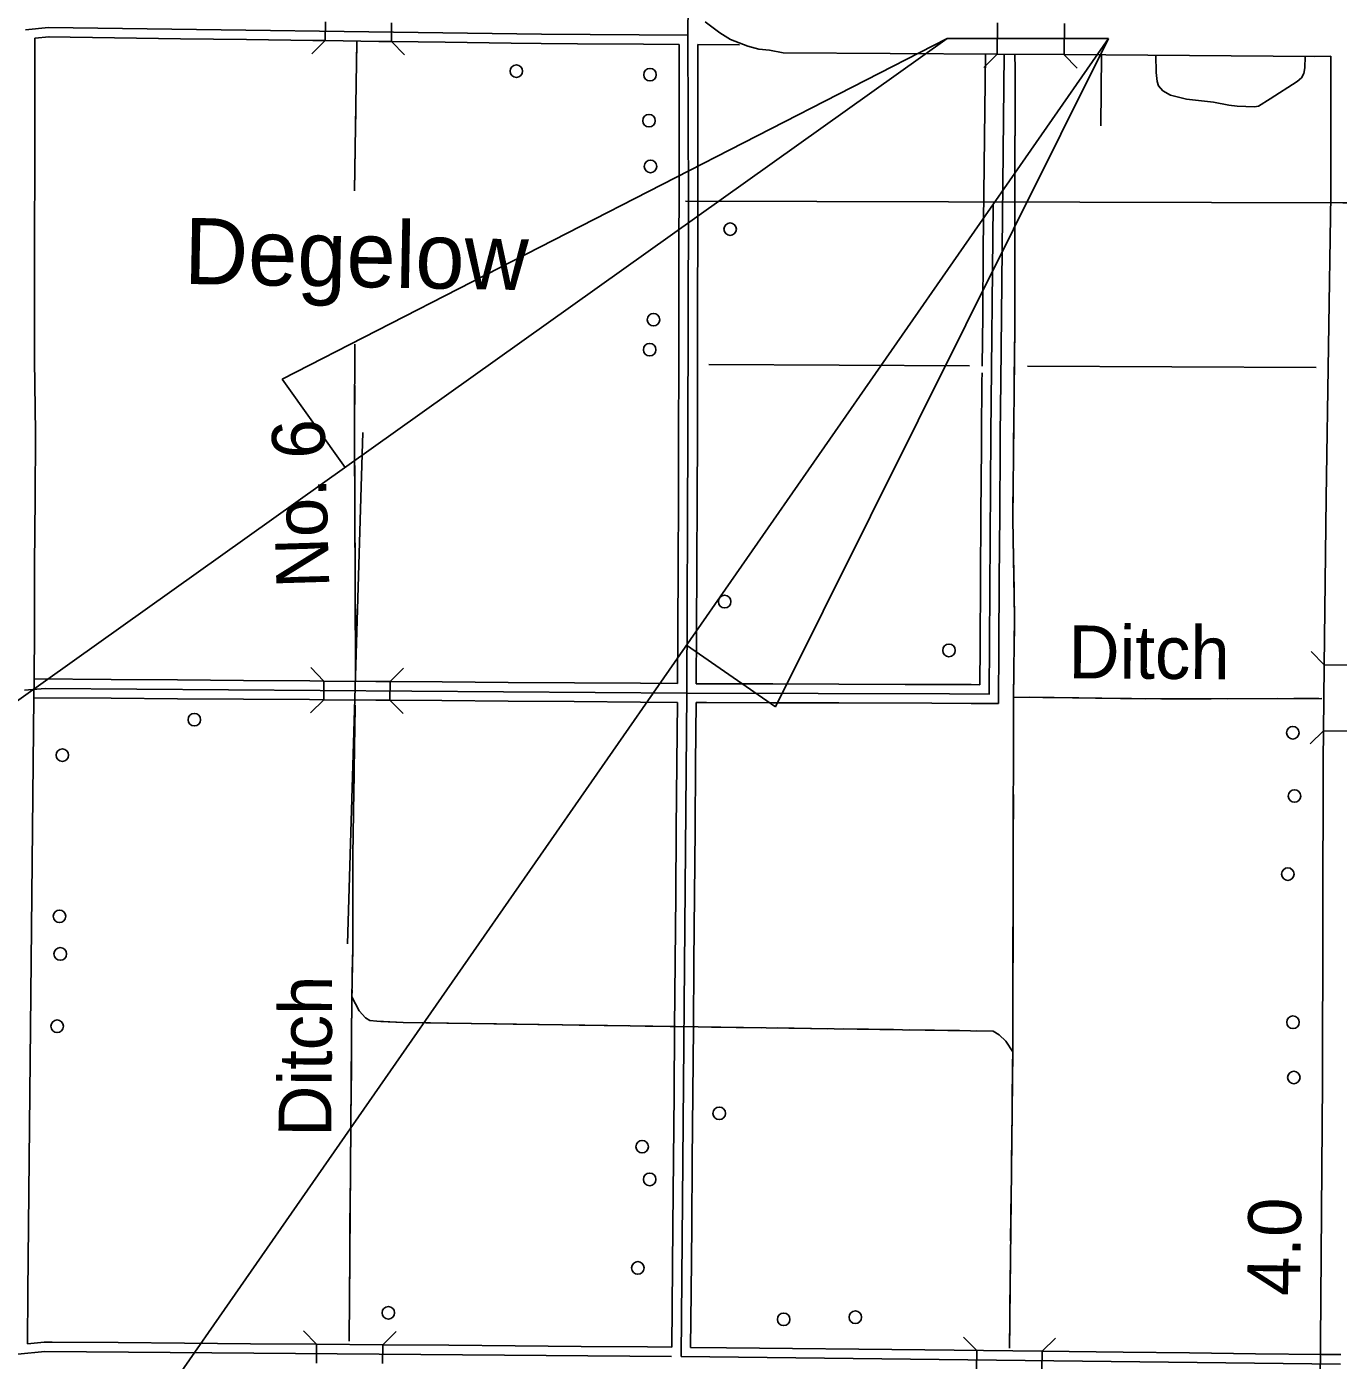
# Model space of a CAD drawing. Extents: x -4306 to 3843, y 131 to 8053.
# Drawn here: x -1926 to -251, y 1950 to 3654 of the extents above; entities that cross this region are included whole.
import ezdxf

# ---------------------------------------------------------------- set-up
doc = ezdxf.new("R2010")
doc.units = 0
for name, color, linetype in [('10', 7, 'Continuous'), ('24', 7, 'Continuous'), ('31', 7, 'Continuous'), ('32', 7, 'Continuous'), ('33', 7, 'Continuous'), ('35', 7, 'Continuous'), ('37', 7, 'Continuous'), ('38', 7, 'Continuous'), ('43', 7, 'Continuous'), ('48', 7, 'Continuous'), ('5', 7, 'Continuous'), ('56', 7, 'Continuous'), ('6', 7, 'Continuous'), ('R_No Plot', 7, 'Continuous')]:
    doc.layers.add(name, color=color, linetype=linetype)

msp = doc.modelspace()

# ---------------------------------------------------------------- linework, layer by layer
at = {"layer": '10'}
for p, q in [((-1040.8, 3645.6), (-1059.8, 3659.7)), ((-686.3, 3658.5), (-686.6, 3618.5)), ((-600.7, 3657.9), (-601, 3617.9)), ((-1027.4, 3637.4), (-1040.8, 3645.6)), ((-1005, 3628.7), (-1027.4, 3637.4)), ((-991.1, 3624.8), (-1005, 3628.7)), ((-977.5, 3623.7), (-991.1, 3624.8)), ((-959.9, 3620.4), (-977.5, 3623.7)), ((-686.6, 3618.5), (-959.9, 3620.4)), ((-687.1, 3618.5), (-600.9, 3617.9)), ((-601, 3617.9), (-281, 3615.7)), ((-281, 3615.7), (-260.7, 3616)), ((-260.7, 3616), (-260.6, 3613.9)), ((-260.6, 3613.9), (-260.3, 3438.2)), ((-260.3, 3438.2), (-266.6, 3051.5)), ((-269.9, 2753.7), (-269, 2836.4)), ((-229, 2837.7), (-269, 2838.1)), ((-269.9, 2754), (-229.9, 2753.6))]:
    msp.add_line(p, q, dxfattribs=at)
for points in [[(-269, 2836.4), (-266.6, 3051.5)], [(-314.4, 293.8), (-314.5, 305.1), (-312.3, 441.3), (-305.4, 600.9), (-302, 628.3), (-293.8, 664.7), (-283.6, 735.2), (-284.1, 861.9), (-282.2, 1054.1), (-278.9, 1201.3), (-280.3, 1434.8), (-278.7, 1599.9), (-273.4, 1758.6), (-274.2, 1917.6), (-271, 2305.4), (-270.3, 2716.6), (-269.9, 2753.7)]]:
    msp.add_lwpolyline(points, dxfattribs=at)
at = {"layer": '31'}
for p, q in [((-1545.1, 3635.8), (-1544.8, 3659.8)), ((-1460.5, 3634.7), (-1460.2, 3658.7)), ((-1915.8, 3638.8), (-1897.4, 3640.6)), ((-1898.7, 3640.5), (-1814.2, 3639.4)), ((-1814.2, 3639.4), (-1729.7, 3638.3)), ((-1560.8, 3636), (-1545.1, 3635.8)), ((-1545, 3635.8), (-1476.3, 3634.9)), ((-1476.3, 3634.9), (-1460.6, 3634.7)), ((-1460.6, 3634.7), (-1391.8, 3633.8)), ((-1222.8, 3631.8), (-1222.8, 3631.8)), ((-1222.8, 3631.8), (-1138.3, 3631.2)), ((-1138.3, 3631.2), (-1093, 3630.9)), ((-1069, 3630.8), (-1015.9, 3630.4)), ((-1915.9, 3558), (-1916, 3473.5)), ((-1916, 3473.5), (-1916.1, 3389)), ((-1093.1, 3388.4), (-1093, 3429.9)), ((-1069, 3429.9), (-1069, 3429.9)), ((-1916.3, 3227.2), (-1916.1, 3389)), ((-1916.1, 3389), (-1916.1, 3389)), ((-1093.1, 3388.4), (-1093.3, 3304)), ((-1069.1, 3388.4), (-1069.3, 3303.9)), ((-1093.3, 3304), (-1093.4, 3219.5)), ((-1069.3, 3303.9), (-1069.4, 3219.4)), ((-1916.3, 3227.2), (-1915.2, 3135.7)), ((-1915.2, 3135.7), (-1915.2, 3133.4)), ((-1915.2, 3133.4), (-1915.6, 3051)), ((-1093.9, 3050.5), (-1094.3, 2966)), ((-1069.9, 3050.4), (-1070.3, 2965.9)), ((-1094.3, 2966), (-1094.7, 2881.5)), ((-1070.3, 2965.9), (-1070.7, 2881.4)), ((-1916.5, 2882), (-1916.8, 2820.3)), ((-1916.8, 2820.3), (-1917, 2796.3)), ((-1917, 2796.3), (-1917.9, 2713)), ((-1095.8, 2712.6), (-1096.5, 2628.1)), ((-1071.8, 2712.4), (-1072.5, 2627.9)), ((-1096.5, 2628.1), (-1097.2, 2543.6)), ((-1072.5, 2627.9), (-1073.2, 2543.4)), ((-1919.6, 2544), (-1920.4, 2459.6)), ((-1920.4, 2459.6), (-1921.3, 2375.1)), ((-1098.7, 2374.7), (-1099.4, 2290.2)), ((-1074.7, 2374.5), (-1075.4, 2290)), ((-1099.4, 2290.2), (-1100.1, 2205.7)), ((-1075.4, 2290), (-1076.1, 2205.5)), ((-1923, 2206.1), (-1923.9, 2121.6)), ((-1100.1, 2205.7), (-1100.1, 2205.7)), ((-1923.9, 2121.6), (-1924.7, 2037.1)), ((-1077.6, 2036.5), (-1078.2, 1966.2)), ((-1032.5, 1965.7), (-1078.2, 1966.2)), ((-948, 1964.8), (-1032.5, 1965.7)), ((-629.3, 1961.2), (-779, 1962.9)), ((-713.1, 1938.1), (-712.8, 1962.1)), ((-629.6, 1937.2), (-629.3, 1961.2)), ((-629.3, 1961.2), (-525.6, 1960)), ((-525.6, 1960), (-441.1, 1959.1)), ((-356.6, 1958.1), (-441.1, 1959.1)), ((-272.1, 1957.2), (-356.6, 1958.1)), ((-247.9, 1956.9), (-272.1, 1957.2))]:
    msp.add_line(p, q, dxfattribs=at)
for points in [[(-1074.7, 3724.2), (-1078.5, 3721.7), (-1079.5, 3714.3), (-1081.3, 3682.4), (-1081.6, 3642.9), (-1081, 3429.9), (-1081.6, 3132.7)], [(-1915.9, 3558), (-1915.8, 3638.8)], [(-1729.7, 3638.3), (-1645.3, 3637.2)], [(-1645.3, 3637.2), (-1560.8, 3636)], [(-1391.8, 3633.8), (-1307.3, 3632.6)], [(-1307.3, 3632.6), (-1269.1, 3632.1), (-1222.8, 3631.8)], [(-1069, 3429.9), (-1069, 3429.9), (-1069.1, 3388.4)], [(-1093.4, 3219.5), (-1093.6, 3135)], [(-1069.6, 3134.9), (-1069.4, 3219.4)], [(-1093.6, 3135), (-1093.6, 3132.7), (-1093.9, 3050.5)], [(-1081.6, 3132.7), (-1083, 2802.2), (-1090.3, 1954.4)], [(-1069.9, 3050.4), (-1069.6, 3132.7), (-1069.6, 3134.9)], [(-1916.1, 2966.5), (-1915.6, 3051)], [(-1916.5, 2882), (-1916.1, 2966.5)], [(-1095, 2814.3), (-1094.7, 2881.5)], [(-1070.7, 2881.4), (-1071, 2814.2)], [(-1095.8, 2712.6), (-1095.1, 2790.3)], [(-1071.1, 2790.2), (-1071.8, 2712.4)], [(-1917.9, 2713), (-1918.7, 2628.5)], [(-1918.7, 2628.5), (-1919.6, 2544)], [(-1097.2, 2543.6), (-1098, 2459.2)], [(-1074, 2459), (-1073.2, 2543.4)], [(-1098, 2459.2), (-1098.7, 2374.7)], [(-1074.7, 2374.5), (-1074, 2459)], [(-1922.2, 2290.6), (-1921.3, 2375.1)], [(-1923, 2206.1), (-1922.2, 2290.6)], [(-1100.1, 2205.7), (-1100.9, 2121.2)], [(-1076.8, 2121), (-1076.1, 2205.5)], [(-1100.9, 2121.2), (-1102.2, 1966.5)], [(-1077.6, 2036.5), (-1076.8, 2121)], [(-1924.7, 2037.1), (-1925.4, 1970.7)], [(-863.5, 1963.8), (-948, 1964.8)], [(-779, 1962.9), (-863.5, 1963.8)]]:
    msp.add_lwpolyline(points, dxfattribs=at)
at = {"layer": '32'}
for p, q in [((-1927.7, 3649.7), (-1898.5, 3652.6)), ((-704.4, 3369.4), (-701.8, 3618.6)), ((-680.4, 3369.2), (-677.8, 3618.4)), ((-705.2, 3284.9), (-704.4, 3369.4)), ((-681.2, 3284.7), (-680.4, 3369.2)), ((-705.9, 3219.9), (-705.2, 3284.9)), ((-682.1, 3200.2), (-681.2, 3284.7)), ((-706.1, 3200.4), (-706, 3211.2)), ((-706.8, 3133.1), (-706.1, 3200.4)), ((-682.8, 3132.9), (-682.1, 3200.2)), ((-706.9, 3115.9), (-706.8, 3133.1)), ((-682.9, 3115.7), (-682.8, 3132.9)), ((-707.4, 3031.4), (-706.9, 3115.9)), ((-683.4, 3031.3), (-682.9, 3115.7)), ((-708, 2946.9), (-707.4, 3031.4)), ((-684, 2946.8), (-683.4, 3031.3)), ((-708.5, 2862.4), (-708, 2946.9)), ((-684.5, 2862.3), (-684, 2946.8)), ((-708.8, 2812.9), (-708.5, 2862.4)), ((-685, 2788.9), (-684.5, 2862.3)), ((-1916.8, 2820.3), (-1818.2, 2819.6)), ((-1818.2, 2819.6), (-1733.7, 2819)), ((-1733.7, 2819), (-1649.2, 2818.4)), ((-1649.2, 2818.4), (-1564.7, 2817.8)), ((-1564.7, 2817.8), (-1546.6, 2817.6)), ((-1546.8, 2793.6), (-1546.6, 2817.6)), ((-1546.6, 2817.6), (-1480.2, 2817.1)), ((-1480.2, 2817.1), (-1462.2, 2817)), ((-1462.4, 2793), (-1462.2, 2817)), ((-1462.3, 2817), (-1395.7, 2816.5)), ((-1395.7, 2816.5), (-1311.2, 2815.9)), ((-1311.2, 2815.9), (-1226.7, 2815.3)), ((-1226.7, 2815.3), (-1142.3, 2814.7)), ((-1142.3, 2814.7), (-1095, 2814.3)), ((-1071, 2814.2), (-1057.8, 2814.1)), ((-1057.8, 2814.1), (-973.3, 2813.9)), ((-973.3, 2813.9), (-888.8, 2813.6)), ((-888.8, 2813.6), (-804.4, 2813.3)), ((-804.4, 2813.3), (-747.6, 2813.1)), ((-747.6, 2813.1), (-719.9, 2813)), ((-719.9, 2813), (-708.8, 2812.9)), ((-1928.9, 2805.9), (-1902.7, 2808.2)), ((-1917, 2796.3), (-1818.3, 2795.6)), ((-1818.3, 2795.6), (-1733.8, 2795)), ((-1733.8, 2795), (-1649.4, 2794.4)), ((-1649.4, 2794.4), (-1564.9, 2793.8)), ((-1564.9, 2793.8), (-1546.8, 2793.6)), ((-1546.9, 2793.6), (-1480.4, 2793.1)), ((-1480.4, 2793.1), (-1462.4, 2793)), ((-1462.6, 2793), (-1395.9, 2792.5)), ((-1395.9, 2792.5), (-1311.4, 2791.9)), ((-1311.4, 2791.9), (-1226.9, 2791.3)), ((-1226.9, 2791.3), (-1142.4, 2790.7)), ((-1142.4, 2790.7), (-1095.1, 2790.3)), ((-1071.1, 2790.2), (-1057.9, 2790.1)), ((-1057.9, 2790.1), (-973.4, 2789.8)), ((-973.4, 2789.8), (-888.9, 2789.6)), ((-888.9, 2789.6), (-770.3, 2789.2)), ((-770.3, 2789.2), (-719.9, 2789)), ((-719.9, 2789), (-685, 2788.9)), ((-1925.4, 1970.7), (-1903.9, 1973)), ((-1903.9, 1973), (-1893.9, 1972.9)), ((-1893.9, 1972.9), (-1809.4, 1972.3)), ((-1809.4, 1972.3), (-1724.9, 1971.6)), ((-1724.9, 1971.6), (-1640.4, 1970.9)), ((-1640.4, 1970.9), (-1555.9, 1970.2)), ((-1556.1, 1946.2), (-1555.9, 1970.2)), ((-1555.9, 1970.2), (-1471.4, 1969.5)), ((-1471.6, 1945.5), (-1471.4, 1969.5)), ((-1471.4, 1969.5), (-1386.9, 1968.8)), ((-1386.9, 1968.8), (-1302.4, 1968.1)), ((-1302.4, 1968.1), (-1218, 1967.4)), ((-1218, 1967.4), (-1133.5, 1966.7)), ((-1133.5, 1966.7), (-1102.2, 1966.5)), ((-248.2, 1944.9), (-1090.3, 1954.4))]:
    msp.add_line(p, q, dxfattribs=at)
for points in [[(-1898.5, 3652.6), (-1268.9, 3644.1)], [(-1268.9, 3644.1), (-1081.6, 3642.9)], [(-694.8, 3133), (-691.8, 3425.9)], [(-747.7, 2801.1), (-696.9, 2800.9), (-694.8, 3133)], [(-1902.7, 2808.2), (-1083, 2802.2), (-747.7, 2801.1)], [(-2400.7, 1957.8), (-1937.5, 1957.3), (-1903.3, 1961)], [(-1903.3, 1961), (-1102.5, 1954.5)]]:
    msp.add_lwpolyline(points, dxfattribs=at)
at = {"layer": '33'}
for p, q in [((-1093, 3630.9), (-1093, 3429.9)), ((-1069, 3630.8), (-1069, 3429.9)), ((-553.4, 3617.5), (-554.1, 3527)), ((-483.8, 3594.9), (-484, 3617.1)), ((-293.2, 3615.7), (-293.7, 3601.2)), ((-293.7, 3601.2), (-295.1, 3593.8)), ((-482.5, 3583.7), (-483.8, 3594.9)), ((-480.7, 3578.1), (-482.5, 3583.7)), ((-303.4, 3583.5), (-338, 3561.3)), ((-297.9, 3588.5), (-303.4, 3583.5)), ((-295.1, 3593.8), (-297.9, 3588.5)), ((-475.3, 3571.6), (-480.7, 3578.1)), ((-465.4, 3566.2), (-475.3, 3571.6)), ((-444.9, 3561.1), (-465.4, 3566.2)), ((-410.2, 3557), (-444.9, 3561.1)), ((-390.6, 3553.2), (-410.2, 3557)), ((-380, 3551.9), (-390.6, 3553.2)), ((-358.2, 3551.1), (-380, 3551.9)), ((-352.7, 3552.1), (-358.2, 3551.1)), ((-338, 3561.3), (-352.7, 3552.1))]:
    msp.add_line(p, q, dxfattribs=at)
at = {"layer": '35'}
msp.add_lwpolyline([(-272.1, 2795.3), (-477.6, 2794.8), (-665.7, 2797)], dxfattribs=at)
at = {"layer": '37'}
for p, q in [((-686.5, 3638.5), (-686.5, 3638.5)), ((-601.3, 3637.9), (-601.3, 3637.9))]:
    msp.add_line(p, q, dxfattribs=at)
for points in [[(-703.7, 3601.6), (-686.6, 3618.5)], [(-601.4, 3617.9), (-584.6, 3600.8)], [(-285.7, 2855.3), (-269, 2838.1)], [(-269.9, 2754), (-287, 2737.2)]]:
    msp.add_lwpolyline(points, dxfattribs=at)
at = {"layer": '38'}
for p, q in [((-1546.7, 2805.6), (-1546.7, 2805.6)), ((-1462.3, 2805), (-1462.3, 2805))]:
    msp.add_line(p, q, dxfattribs=at)
for points in [[(-1545, 3635.8), (-1562.2, 3619.1)], [(-1443.8, 3617.5), (-1460.5, 3634.7)], [(-1546.6, 2817.6), (-1563.5, 2834.7)], [(-1445.1, 2833.9), (-1462.2, 2817)], [(-1563.9, 2776.8), (-1546.8, 2793.6)], [(-1462.4, 2793), (-1445.5, 2775.9)], [(-1572.7, 1987.3), (-1555.9, 1970.2)], [(-1471.4, 1969.5), (-1454.3, 1986.3)], [(-729.6, 1979.3), (-712.8, 1962.1)], [(-629.3, 1961.2), (-612.1, 1978)]]:
    msp.add_lwpolyline(points, dxfattribs=at)
at = {"layer": '43'}
for points in [[(-1504.5, 3635.3), (-1507.7, 3443.8)], [(-1504.5, 3635.3), (-1505, 3603.6)], [(-664.2, 3429.5), (-663.8, 3599.9), (-664.2, 3618.3)], [(-663.9, 3566.8), (-663.8, 3599.9), (-664.2, 3618.3)], [(-1505.4, 3582.5), (-1506.5, 3519.1)], [(-664.1, 3482.3), (-663.9, 3545.6)], [(-1506.8, 3498), (-1507.7, 3443.8)], [(-664.2, 3429.5), (-664.2, 3461.2)], [(-665.7, 2797), (-664.4, 2899.3), (-666.9, 3024.6), (-664.2, 3269.6), (-664.2, 3429.5)], [(-664.2, 3356.7), (-664.2, 3420.1)], [(-664.2, 3303.9), (-664.2, 3335.6)], [(-664.2, 3272.2), (-664.2, 3303.9)], [(-1507.1, 3248), (-1507.6, 3146.3), (-1506.3, 2829.3)], [(-1507.1, 3248), (-1507.2, 3216.3)], [(-665.1, 3187.7), (-664.4, 3251.1)], [(-1507.3, 3195.2), (-1507.6, 3146.3), (-1507.5, 3131.8)], [(-666, 3103.2), (-665.3, 3166.6)], [(-1496.8, 3135), (-1498.9, 3065.5)], [(-1507.5, 3110.7), (-1507.2, 3047.3)], [(-666.8, 3018.8), (-666.9, 3024.6), (-666.3, 3082.1)], [(-1498.9, 3065.5), (-1516.5, 2482)], [(-1507.1, 3026.2), (-1506.9, 2962.9)], [(-665.1, 2934.3), (-666.4, 2997.6)], [(-1506.8, 2941.7), (-1506.5, 2878.4)], [(-665, 2849.8), (-664.4, 2899.3), (-664.7, 2913.2)], [(-1506.4, 2857.2), (-1506.3, 2829.3)], [(-665.7, 2797), (-665.3, 2828.7)], [(-671, 1965), (-666.9, 2343.9), (-665.7, 2797)], [(-276, 2795.3), (-477.6, 2794.8), (-665.7, 2797)], [(-665.7, 2778.2), (-665.7, 2797)], [(-582.3, 2796), (-645.6, 2796.8)], [(-497.8, 2795), (-561.1, 2795.8)], [(-413.3, 2795), (-476.7, 2794.8)], [(-328.8, 2795.2), (-392.2, 2795)], [(-276, 2795.3), (-307.7, 2795.2)], [(-1506.6, 2786.8), (-1509.9, 2594.6), (-1509.8, 2476)], [(-1506.6, 2786.8), (-1507.1, 2755.1)], [(-666, 2693.7), (-665.8, 2757.1)], [(-1507.5, 2734), (-1508.6, 2670.6)], [(-666.2, 2609.2), (-666, 2672.6)], [(-1508.9, 2649.5), (-1509.9, 2594.6), (-1509.9, 2586.2)], [(-666.4, 2524.7), (-666.2, 2588.1)], [(-1509.8, 2565), (-1509.8, 2501.7)], [(-666.6, 2471.9), (-666.5, 2503.6)], [(-1509.8, 2476), (-1510.9, 2414), (-1514.5, 1974.3)], [(-1509.8, 2476), (-1510.4, 2444.3)], [(-1509.8, 2480.5), (-1509.8, 2476)], [(-666.7, 2440.2), (-666.6, 2471.9)], [(-1510.7, 2423.2), (-1510.9, 2414), (-1511.3, 2359.8)], [(-1510.9, 2414), (-1501.8, 2396), (-1493.5, 2387.1), (-1488, 2383.9), (-1479.1, 2383), (-1445.5, 2381.2), (-692, 2370.4), (-684, 2365.6), (-675.6, 2357.3), (-666.9, 2343.9)], [(-1510.9, 2414), (-1501.8, 2396), (-1493.9, 2387.6)], [(-666.9, 2355.8), (-666.7, 2419.1)], [(-1473.9, 2382.7), (-1445.5, 2381.2), (-1410.6, 2380.7)], [(-1389.5, 2380.4), (-1326.1, 2379.5)], [(-1305, 2379.2), (-1241.7, 2378.3)], [(-1220.5, 2378), (-1157.2, 2377)], [(-1136.1, 2376.7), (-1072.7, 2375.8)], [(-1051.6, 2375.5), (-1019.9, 2375.1)], [(-1019.9, 2375.1), (-988.2, 2374.6)], [(-967.1, 2374.3), (-903.7, 2373.4)], [(-882.6, 2373.1), (-819.3, 2372.2)], [(-798.1, 2371.9), (-734.8, 2371)], [(-713.7, 2370.7), (-692, 2370.4), (-684, 2365.6), (-675.6, 2357.3), (-666.9, 2343.9)], [(-1511.5, 2338.7), (-1512, 2275.3)], [(-667.7, 2271.3), (-667, 2334.6)], [(-1512.2, 2254.2), (-1512.7, 2190.8)], [(-668.6, 2186.8), (-667.9, 2250.2)], [(-1512.9, 2169.7), (-1513.4, 2106.4)], [(-669.5, 2102.3), (-668.9, 2165.7)], [(-1513.6, 2085.2), (-1514.1, 2021.9)], [(-670.5, 2017.8), (-669.8, 2081.2)], [(-1514.3, 2000.7), (-1514.5, 1974.3)], [(-671, 1965), (-670.7, 1996.7)]]:
    msp.add_lwpolyline(points, dxfattribs=at)
at = {"layer": '5'}
for p, q in [((-1055.1, 3222.1), (-721.9, 3220.4)), ((-648, 3220), (-279.3, 3218.1))]:
    msp.add_line(p, q, dxfattribs=at)
at = {"layer": '56'}
for centre in [(-1300.8, 3596.8), (-1130.1, 3592.3), (-1131.4, 3533.5), (-1129.5, 3475.1), (-1027.8, 3394.9), (-1125.7, 3279.3), (-1130.5, 3240.9), (-1034.8, 2919.1), (-748.3, 2856.7), (-1712.2, 2768.2), (-309.1, 2751.5), (-1880.7, 2722.9), (-306.9, 2670.6), (-315.5, 2570.9), (-1884.4, 2517), (-1883.4, 2468.9), (-308.9, 2381.6), (-1887.4, 2376.5), (-307.8, 2311), (-1041.7, 2265.2), (-1140.2, 2222.6), (-1130.5, 2180.8), (-1145.7, 2067.7), (-1464.3, 2010.4), (-867.8, 2004.7), (-959.4, 2002)]:
    msp.add_circle(centre, 8, dxfattribs=at)
at = {"layer": '6'}
msp.add_lwpolyline([(506.8, 3428.7), (-245, 3428.6), (-1084.8, 3430.5)], dxfattribs=at)
at = {"layer": 'R_No Plot'}
for p, q in [((-2855, 2139.1), (-750.7, 3638.5)), ((-2436.2, 918.6), (-544.5, 3638.5)), ((-750.7, 3638.5), (-1599.8, 3203.3)), ((-544.5, 3638.5), (-970, 2784.5)), ((-544.5, 3638.5), (-750.7, 3638.5)), ((-1599.8, 3203.3), (-1519.6, 3090.6)), ((-970, 2784.5), (-1083.5, 2863.4))]:
    msp.add_line(p, q, dxfattribs=at)

# ---------------------------------------------------------------- texts
at = {"layer": '24'}
msp.add_text('Degelow', height=84.49, rotation=358.9554, dxfattribs=at).set_placement((-1725.7, 3325))
at = {"layer": '43'}
for s, rotation, p in [('No. 6', 91.7362, (-1539.6, 2937)), ('Ditch', 359.6372, (-595.8, 2821.1)), ('Ditch', 89.7133, (-1537.1, 2235.2))]:
    msp.add_text(s, height=67.59, rotation=rotation, dxfattribs=at).set_placement(p)
at = {"layer": '48'}
msp.add_text('4.0', height=67.59, rotation=89.1807, dxfattribs=at).set_placement((-299.9, 2031.5))

doc.saveas('drawing.dxf')
